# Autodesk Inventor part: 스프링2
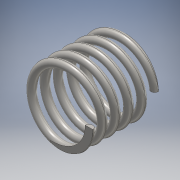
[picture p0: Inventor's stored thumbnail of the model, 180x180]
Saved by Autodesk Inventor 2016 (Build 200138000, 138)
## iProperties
Created: 2019-11
Part Number: 스프링2
Material: 스테인레스 스틸
Document SubType Name: Modeling
Designer: user
Density: 8 g/cm^3
Appearance: 반연마
Mass: 6.54924 g
Surface Area: 16.7049 cm^2
Volume: 0.818655 cm^3
Author: user
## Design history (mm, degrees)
sketch "스케치1"
  geometry: L1 (0, 0)-(8.5, 0); L2 (8.5, 0)-(8.5, 17.5); L3 (8.5, 17.5)-(0, 17.5); L4 (0, 17.5)-(0, 0); C1 r 1 at (8.5, 0)
  constraints: 8 end point, 2 parallel, 1 centre point, 1 coincident, 1 horizontal, 1 perpendicular
  dimensions: "d0" = 17 diameter of L2 L4; "d1" = 2 diameter of C1; "d2" = 17.5 distance of L1.end L2.end (derived)
feature "코일1" sketch "스케치1" pitch "d3" = 10; turns "d5" = 5; dims "d4" = 17.5 (= d2), "d6" = 0, angle "d7" = 90 deg, angle "d8" = 90 deg, "d9" = 0, "d10" = 0
sketch "스케치2"
  geometry: L1 (-15.597, 17.5)-(15.597, 17.5); L2 (15.597, 17.5)-(15.597, 0); L3 (15.597, 0)-(-15.597, 0); L4 (-15.597, 0)-(-15.597, 17.5); 2 further points
  constraints: 8 end point, 2 parallel, 1 coincident, 1 horizontal, 1 midpoint, 1 perpendicular
  dimensions: "d11" = 17.5 distance of L1.end L2.end (= d2)
extrude "돌출1" sketch "스케치2" stored distance "d12" = 50; taper "d13" = 0 deg
node "솔리드1"
